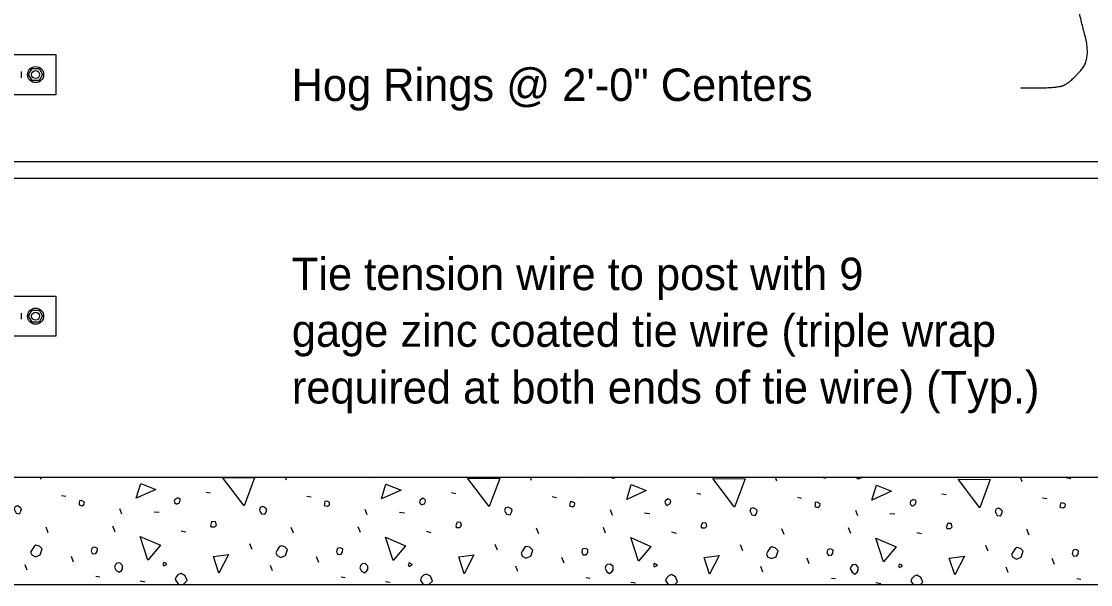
# Model space of a CAD drawing. Extents: x 0 to 41.1, y 0 to 26.4.
# Drawn here: x 12.4 to 19.04, y 13.8 to 17.3 of the extents above; entities that cross this region are included whole.
import ezdxf

# ---------------------------------------------------------------- set-up
doc = ezdxf.new("R2010")
doc.units = 0
for name, color, linetype in [('Dimension', 7, 'Continuous'), ('Miscellaneous', 7, 'Continuous'), ('SteelMisc', 7, 'Continuous'), ('SupstrConc', 7, 'Continuous'), ('TextStructures', 7, 'Continuous')]:
    doc.layers.add(name, color=color, linetype=linetype)

msp = doc.modelspace()

# ---------------------------------------------------------------- linework, layer by layer
at = {"layer": 'Dimension'}
msp.add_open_spline([(18.6095, 16.8868), (18.8324, 16.8833), (18.9173, 16.9222), (19.0482, 17.0709), (18.9633, 17.3684), (18.9208, 17.6337)], degree=2, dxfattribs=at)
at = {"layer": 'Miscellaneous'}
for p, q in [((12.5219, 14.4553), (12.5167, 14.4695)), ((14.0457, 14.4518), (14.0392, 14.4695)), ((15.5695, 14.4482), (15.5617, 14.4695)), ((15.8647, 14.4695), (15.8718, 14.4677)), ((17.0933, 14.4447), (17.0842, 14.4695)), ((17.3744, 14.4695), (17.3956, 14.4641)), ((18.6171, 14.4412), (18.6067, 14.4695)), ((18.8911, 14.4677), (18.9194, 14.4606)), ((12.6492, 14.3563), (12.6757, 14.351)), ((13.5472, 14.3775), (13.5737, 14.3722)), ((14.173, 14.3528), (14.1995, 14.3475)), ((15.071, 14.374), (15.0975, 14.3687)), ((16.5948, 14.3705), (16.6213, 14.3652)), ((18.1186, 14.3669), (18.1451, 14.3616)), ((15.6968, 14.3492), (15.7233, 14.3439)), ((17.2206, 14.3457), (17.2471, 14.3404)), ((18.7444, 14.3422), (18.7709, 14.3369)), ((13.0239, 14.2396), (13.0115, 14.2732)), ((13.2237, 14.2556), (13.2555, 14.252)), ((14.5477, 14.2361), (14.5354, 14.2697)), ((14.7475, 14.252), (14.7793, 14.2485)), ((16.0716, 14.2326), (16.0592, 14.2662)), ((16.2713, 14.2485), (16.3031, 14.2449)), ((17.5954, 14.229), (17.583, 14.2626)), ((17.7951, 14.2449), (17.8269, 14.2414)), ((12.5661, 14.1247), (12.5519, 14.1601)), ((12.9815, 14.13), (12.9674, 14.1654)), ((14.0899, 14.1212), (14.0757, 14.1566)), ((14.5053, 14.1265), (14.4912, 14.1619)), ((15.6137, 14.1177), (15.5996, 14.153)), ((16.0291, 14.123), (16.015, 14.1583)), ((17.5529, 14.1194), (17.5388, 14.1548)), ((13.3916, 14.1371), (13.4199, 14.13)), ((14.9154, 14.1336), (14.9437, 14.1265)), ((16.4392, 14.13), (16.4675, 14.123)), ((17.1375, 14.1141), (17.1234, 14.1495)), ((17.9631, 14.1265), (17.9913, 14.1194)), ((18.6613, 14.1106), (18.6472, 14.146)), ((13.8336, 14.0204), (13.8194, 14.0558)), ((15.3574, 14.0169), (15.3432, 14.0523)), ((16.8812, 14.0134), (16.867, 14.0487)), ((18.405, 14.0098), (18.3909, 14.0452)), ((12.7234, 13.9427), (12.7093, 13.978)), ((14.2472, 13.9391), (14.2331, 13.9745)), ((15.771, 13.9356), (15.7569, 13.9709)), ((17.2948, 13.9321), (17.2807, 13.9674)), ((18.8187, 13.9285), (18.8045, 13.9639)), ((12.4353, 13.8914), (12.4229, 13.925)), ((13.9591, 13.8879), (13.9467, 13.9214)), ((15.4829, 13.8843), (15.4705, 13.9179)), ((17.0067, 13.8808), (16.9943, 13.9144)), ((18.5305, 13.8772), (18.5181, 13.9108)), ((12.8613, 13.8543), (12.886, 13.8507)), ((13.1371, 13.826), (13.1671, 13.8207)), ((14.3851, 13.8507), (14.4099, 13.8472)), ((14.6609, 13.8224), (14.6909, 13.8171)), ((15.9089, 13.8472), (15.9337, 13.8437)), ((16.1847, 13.8189), (16.2147, 13.8136)), ((17.4327, 13.8437), (17.4575, 13.8401)), ((18.9565, 13.8401), (18.9813, 13.8366)), ((17.7085, 13.8154), (17.7386, 13.8101))]:
    msp.add_line(p, q, dxfattribs=at)
for points in [[(13.1123, 14.3386), (13.1406, 14.4306), (13.2343, 14.3934), (13.1123, 14.3386)], [(13.7823, 14.2909), (13.6479, 14.4677), (13.8477, 14.4659), (13.7823, 14.2909)], [(14.5442, 14.4695), (14.5566, 14.4677), (14.5607, 14.4695)], [(14.6361, 14.3351), (14.6644, 14.427), (14.7581, 14.3899), (14.6361, 14.3351)], [(15.3061, 14.2874), (15.1718, 14.4641), (15.3715, 14.4624), (15.3061, 14.2874)], [(16.0645, 14.4695), (16.068, 14.4659)], [(16.068, 14.4659), (16.0804, 14.4641), (16.0928, 14.4695)], [(16.1599, 14.3316), (16.1882, 14.4235), (16.2819, 14.3864), (16.1599, 14.3316)], [(16.8299, 14.2838), (16.6956, 14.4606), (16.8953, 14.4588), (16.8299, 14.2838)], [(17.5848, 14.4695), (17.5918, 14.4624)], [(17.5918, 14.4624), (17.6042, 14.4606), (17.6166, 14.4659), (17.6178, 14.4695)], [(17.6838, 14.328), (17.712, 14.42), (17.8057, 14.3828), (17.6838, 14.328)], [(18.3537, 14.2803), (18.2194, 14.4571), (18.4191, 14.4553), (18.3537, 14.2803)], [(12.3575, 14.2626), (12.3663, 14.2467), (12.3875, 14.2432), (12.3964, 14.2591), (12.3999, 14.2732), (12.3911, 14.2821), (12.3752, 14.2909), (12.3592, 14.2856), (12.3539, 14.2697), (12.3575, 14.2626)], [(12.757, 14.298), (12.7764, 14.2927), (12.7888, 14.3015), (12.7906, 14.3139), (12.787, 14.3174), (12.7729, 14.3245), (12.7605, 14.3227), (12.7588, 14.3104), (12.757, 14.298)], [(13.3598, 14.3033), (13.3669, 14.3033), (13.381, 14.3104), (13.3863, 14.3263), (13.3845, 14.3351), (13.3704, 14.3422), (13.3527, 14.3316), (13.3492, 14.321), (13.3527, 14.3104), (13.3598, 14.3033)], [(13.8813, 14.2591), (13.8901, 14.2432), (13.9113, 14.2396), (13.9202, 14.2556), (13.9237, 14.2697), (13.9149, 14.2785), (13.899, 14.2874), (13.8831, 14.2821), (13.8778, 14.2662), (13.8813, 14.2591)], [(14.2808, 14.2944), (14.3003, 14.2891), (14.3126, 14.298), (14.3144, 14.3104), (14.3109, 14.3139), (14.2967, 14.321), (14.2843, 14.3192), (14.2826, 14.3068), (14.2808, 14.2944)], [(14.8836, 14.2997), (14.8907, 14.2997), (14.9048, 14.3068), (14.9101, 14.3227), (14.9084, 14.3316), (14.8942, 14.3386), (14.8765, 14.328), (14.873, 14.3174), (14.8765, 14.3068), (14.8836, 14.2997)], [(15.4051, 14.2556), (15.4139, 14.2396), (15.4352, 14.2361), (15.444, 14.252), (15.4475, 14.2662), (15.4387, 14.275), (15.4228, 14.2838), (15.4069, 14.2785), (15.4016, 14.2626), (15.4051, 14.2556)], [(15.8046, 14.2909), (15.8241, 14.2856), (15.8364, 14.2944), (15.8382, 14.3068), (15.8347, 14.3104), (15.8205, 14.3174), (15.8082, 14.3157), (15.8064, 14.3033), (15.8046, 14.2909)], [(16.4074, 14.2962), (16.4145, 14.2962), (16.4286, 14.3033), (16.4339, 14.3192), (16.4322, 14.328), (16.418, 14.3351), (16.4004, 14.3245), (16.3968, 14.3139), (16.4004, 14.3033), (16.4074, 14.2962)], [(17.3284, 14.2874), (17.3479, 14.2821), (17.3603, 14.2909), (17.362, 14.3033), (17.3585, 14.3068), (17.3443, 14.3139), (17.332, 14.3121), (17.3302, 14.2997), (17.3284, 14.2874)], [(17.9312, 14.2927), (17.9383, 14.2927), (17.9525, 14.2997), (17.9578, 14.3157), (17.956, 14.3245), (17.9419, 14.3316), (17.9242, 14.321), (17.9206, 14.3104), (17.9242, 14.2997), (17.9312, 14.2927)], [(18.8523, 14.2838), (18.8717, 14.2785), (18.8841, 14.2874), (18.8858, 14.2997), (18.8823, 14.3033), (18.8682, 14.3104), (18.8558, 14.3086), (18.854, 14.2962), (18.8523, 14.2838)], [(16.9289, 14.252), (16.9378, 14.2361), (16.959, 14.2326), (16.9678, 14.2485), (16.9713, 14.2626), (16.9625, 14.2715), (16.9466, 14.2803), (16.9307, 14.275), (16.9254, 14.2591), (16.9289, 14.252)], [(18.4527, 14.2485), (18.4616, 14.2326), (18.4828, 14.229), (18.4916, 14.2449), (18.4952, 14.2591), (18.4863, 14.2679), (18.4704, 14.2768), (18.4545, 14.2715), (18.4492, 14.2556), (18.4527, 14.2485)], [(13.579, 14.1619), (13.6002, 14.1619), (13.6108, 14.1725), (13.6055, 14.1919), (13.5825, 14.1937), (13.579, 14.1831), (13.5737, 14.1742), (13.579, 14.1619), (13.5755, 14.1654)], [(15.1028, 14.1583), (15.124, 14.1583), (15.1346, 14.1689), (15.1293, 14.1884), (15.1064, 14.1901), (15.1028, 14.1795), (15.0975, 14.1707), (15.1028, 14.1583), (15.0993, 14.1619)], [(16.6266, 14.1548), (16.6478, 14.1548), (16.6585, 14.1654), (16.6531, 14.1848), (16.6302, 14.1866), (16.6266, 14.176), (16.6213, 14.1672), (16.6266, 14.1548), (16.6231, 14.1583)], [(18.1504, 14.1513), (18.1717, 14.1513), (18.1823, 14.1619), (18.177, 14.1813), (18.154, 14.1831), (18.1504, 14.1725), (18.1451, 14.1636), (18.1504, 14.1513), (18.1469, 14.1548)], [(13.1848, 13.955), (13.1371, 14.1018), (13.2626, 14.047), (13.1848, 13.955)], [(14.7086, 13.9515), (14.6609, 14.0982), (14.7864, 14.0434), (14.7086, 13.9515)], [(16.2324, 13.948), (16.1847, 14.0947), (16.3102, 14.0399), (16.2324, 13.948)], [(17.7562, 13.9444), (17.7085, 14.0911), (17.834, 14.0363), (17.7562, 13.9444)], [(12.4635, 13.9869), (12.4865, 13.9745), (12.5166, 13.9869), (12.5289, 14.024), (12.5113, 14.0417), (12.4883, 14.047), (12.4777, 14.0399), (12.4653, 14.0204), (12.4565, 14.0045), (12.4635, 13.9869)], [(12.833, 14.0098), (12.8418, 13.9939), (12.8613, 13.9957), (12.8701, 14.0081), (12.8719, 14.0275), (12.8595, 14.0328), (12.8507, 14.0346), (12.8401, 14.031), (12.8365, 14.0275), (12.833, 14.0098)], [(13.9874, 13.9833), (14.0103, 13.9709), (14.0404, 13.9833), (14.0528, 14.0204), (14.0351, 14.0381), (14.0121, 14.0434), (14.0015, 14.0363), (13.9891, 14.0169), (13.9803, 14.001), (13.9874, 13.9833)], [(14.3568, 14.0063), (14.3657, 13.9904), (14.3851, 13.9922), (14.3939, 14.0045), (14.3957, 14.024), (14.3833, 14.0293), (14.3745, 14.031), (14.3639, 14.0275), (14.3604, 14.024), (14.3568, 14.0063)], [(15.5112, 13.9798), (15.5342, 13.9674), (15.5642, 13.9798), (15.5766, 14.0169), (15.5589, 14.0346), (15.5359, 14.0399), (15.5253, 14.0328), (15.5129, 14.0134), (15.5041, 13.9975), (15.5112, 13.9798)], [(15.8806, 14.0028), (15.8895, 13.9869), (15.9089, 13.9886), (15.9178, 14.001), (15.9195, 14.0204), (15.9072, 14.0257), (15.8983, 14.0275), (15.8877, 14.024), (15.8842, 14.0204), (15.8806, 14.0028)], [(17.035, 13.9762), (17.058, 13.9639), (17.088, 13.9762), (17.1004, 14.0134), (17.0827, 14.031), (17.0597, 14.0363), (17.0491, 14.0293), (17.0368, 14.0098), (17.0279, 13.9939), (17.035, 13.9762)], [(17.4044, 13.9992), (17.4133, 13.9833), (17.4327, 13.9851), (17.4416, 13.9975), (17.4433, 14.0169), (17.431, 14.0222), (17.4221, 14.024), (17.4115, 14.0204), (17.408, 14.0169), (17.4044, 13.9992)], [(18.5588, 13.9727), (18.5818, 13.9603), (18.6118, 13.9727), (18.6242, 14.0098), (18.6065, 14.0275), (18.5836, 14.0328), (18.5729, 14.0257), (18.5606, 14.0063), (18.5517, 13.9904), (18.5588, 13.9727)], [(18.9283, 13.9957), (18.9371, 13.9798), (18.9565, 13.9815), (18.9654, 13.9939), (18.9672, 14.0134), (18.9548, 14.0187), (18.9459, 14.0204), (18.9353, 14.0169), (18.9318, 14.0134), (18.9283, 13.9957)], [(13.6267, 13.8737), (13.5931, 13.978), (13.6868, 13.9904), (13.6267, 13.8737)], [(15.1505, 13.8702), (15.117, 13.9745), (15.2107, 13.9869), (15.1505, 13.8702)], [(16.6744, 13.8666), (16.6408, 13.9709), (16.7345, 13.9833), (16.6744, 13.8666)], [(18.1982, 13.8631), (18.1646, 13.9674), (18.2583, 13.9798), (18.1982, 13.8631)], [(12.978, 13.9108), (12.9886, 13.8896), (13.0062, 13.879), (13.0204, 13.8896), (13.0275, 13.9002), (13.0275, 13.9214), (13.0115, 13.9374), (12.9921, 13.9356), (12.9833, 13.9267), (12.978, 13.9108)], [(13.2838, 13.9197), (13.3032, 13.9285), (13.2962, 13.9356), (13.2838, 13.9409), (13.2785, 13.9285), (13.2838, 13.9197)], [(14.5018, 13.9073), (14.5124, 13.8861), (14.5301, 13.8755), (14.5442, 13.8861), (14.5513, 13.8967), (14.5513, 13.9179), (14.5354, 13.9338), (14.5159, 13.9321), (14.5071, 13.9232), (14.5018, 13.9073)], [(14.8076, 13.9161), (14.827, 13.925), (14.82, 13.9321), (14.8076, 13.9374), (14.8023, 13.925), (14.8076, 13.9161)], [(16.0256, 13.9038), (16.0362, 13.8826), (16.0539, 13.8719), (16.068, 13.8826), (16.0751, 13.8932), (16.0751, 13.9144), (16.0592, 13.9303), (16.0397, 13.9285), (16.0309, 13.9197), (16.0256, 13.9038)], [(16.3314, 13.9126), (16.3509, 13.9214), (16.3438, 13.9285), (16.3314, 13.9338), (16.3261, 13.9214), (16.3314, 13.9126)], [(17.5494, 13.9002), (17.56, 13.879), (17.5777, 13.8684), (17.5918, 13.879), (17.5989, 13.8896), (17.5989, 13.9108), (17.583, 13.9267), (17.5635, 13.925), (17.5547, 13.9161), (17.5494, 13.9002)], [(17.8552, 13.9091), (17.8747, 13.9179), (17.8676, 13.925), (17.8552, 13.9303), (17.8499, 13.9179), (17.8552, 13.9091)], [(13.4038, 13.8028), (13.4093, 13.8083), (13.4287, 13.8278), (13.4164, 13.8578), (13.3916, 13.8719), (13.3739, 13.8649), (13.3598, 13.8507), (13.3545, 13.8348)], [(13.3545, 13.8348), (13.3743, 13.8028)], [(14.9311, 13.8028), (14.9331, 13.8048), (14.9526, 13.8242), (14.9402, 13.8543), (14.9154, 13.8684), (14.8978, 13.8613), (14.8836, 13.8472), (14.8783, 13.8313)], [(14.8783, 13.8313), (14.896, 13.8028)], [(16.4585, 13.8028), (16.4764, 13.8207), (16.464, 13.8507), (16.4392, 13.8649), (16.4216, 13.8578), (16.4074, 13.8437), (16.4021, 13.8278)], [(16.4021, 13.8278), (16.4176, 13.8028)], [(17.9858, 13.8028), (18.0002, 13.8171), (17.9878, 13.8472), (17.9631, 13.8613), (17.9454, 13.8543), (17.9312, 13.8401), (17.9259, 13.8242)], [(17.9259, 13.8242), (17.9392, 13.8028)]]:
    msp.add_lwpolyline(points, dxfattribs=at)
at = {"layer": 'SteelMisc'}
for p, q in [((11.8002, 17.0944), (12.6122, 17.0944)), ((12.6122, 17.0944), (12.6122, 16.8444)), ((12.399, 16.95), (12.399, 16.9889)), ((12.6122, 16.8444), (11.8002, 16.8444)), ((11.8002, 15.5944), (12.6122, 15.5944)), ((12.6122, 15.5944), (12.6122, 15.3444)), ((12.399, 15.45), (12.399, 15.4889)), ((12.6122, 15.3444), (11.8002, 15.3444))]:
    msp.add_line(p, q, dxfattribs=at)
for points in [[(12.4655, 17.007), (12.5089, 17.007), (12.5305, 16.9694), (12.5089, 16.9319), (12.4655, 16.9319), (12.4439, 16.9694)], [(12.4655, 15.507), (12.5089, 15.507), (12.5305, 15.4694), (12.5089, 15.4319), (12.4655, 15.4319), (12.4439, 15.4694)]]:
    msp.add_lwpolyline(points, close=True, dxfattribs=at)
for centre, radius in [((12.4872, 16.9694), 0.05), ((12.4872, 16.9694), 0.025), ((12.4872, 15.4694), 0.05), ((12.4872, 15.4694), 0.025)]:
    msp.add_circle(centre, radius, dxfattribs=at)
at = {"layer": 'SupstrConc'}
for p, q in [((12.3521, 16.4295), (22.0604, 16.4295)), ((12.3521, 16.3254), (22.0604, 16.3254)), ((0.8193, 14.4695), (23.5931, 14.4695)), ((0.8193, 13.8028), (23.5931, 13.8028))]:
    msp.add_line(p, q, dxfattribs=at)

# ---------------------------------------------------------------- texts
at = {"layer": 'Dimension'}
for s, p in [('Tie tension wire to post with 9 ', (14.0794, 15.6312)), ('gage zinc coated tie wire (triple wrap ', (14.0794, 15.2792)), ('required at both ends of tie wire) (Typ.)', (14.0794, 14.9272))]:
    msp.add_text(s, height=0.2016, dxfattribs=at).set_placement(p)
at = {"layer": 'TextStructures'}
msp.add_text('Hog Rings @ 2\'-0" Centers', height=0.2016, dxfattribs=at).set_placement((14.0777, 16.8056))

doc.saveas('drawing.dxf')
